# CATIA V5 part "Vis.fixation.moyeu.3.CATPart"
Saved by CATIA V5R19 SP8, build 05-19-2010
Part number: Vis.fixation.moyeu.3
Bounding box of the stored display mesh (mm): x -24 to -18, y -1.5 to 1.5, z -1.5 to 1.5
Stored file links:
  G:\EU_thinkMotion\CFAO_2010\MMS_groupe3\MMS_groupe3\jbonnamy\jbonnamy_cfao\Vis.fixation.moyeu.3.CATPart
  C:\Users\Micheline\Desktop\projet CFAO\Nouveau dossier\temp\Nouveau dossier\Vis.fixation.CATPart
  G:\EU_thinkMotion\CFAO_2010\MMS_groupe3\MMS_groupe3\jbonnamy\jbonnamy_cfao\jbonnamy_suspension.arriere.directionnelle.CATProduct
  G:\EU_thinkMotion\CFAO_2010\MMS_groupe3\MMS_groupe3\jbonnamy\jbonnamy_cfao\Vis.fixation.moyeu.2.CATPart
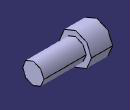
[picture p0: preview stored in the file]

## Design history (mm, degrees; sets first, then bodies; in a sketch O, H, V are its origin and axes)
External parameters (linked from other documents)
  External.Epaisseur.support.10 = 1.5 mm
  External.Diametre.vis.fixation = 2 mm
Set1
  DatumSurface1: linked copy from another document
Body1 (main body)
  Sketch1 on DatumSurface1, origin (-22, 0, 0), H (0, -1, 0), V (0, 0, 1)
    circle A1 centre (0, 0) radius 1
    radius A1 = 1 {= External.Diametre.vis.fixation /2}
  Pad1: profile Sketch1, direction (1, 0, 0), length 4 {= 2*External.Epaisseur.support.10 +1mm}
  Sketch2 on DatumSurface1, origin (-22, 0, 0), H (0, -1, 0), V (0, 0, 1)
    circle A1 centre (0, 0) radius 1.5
    radius A1 = 1.5 {= 3*External.Diametre.vis.fixation /4}
  Pad2: profile Sketch2, direction (-1, 0, 0), length 2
